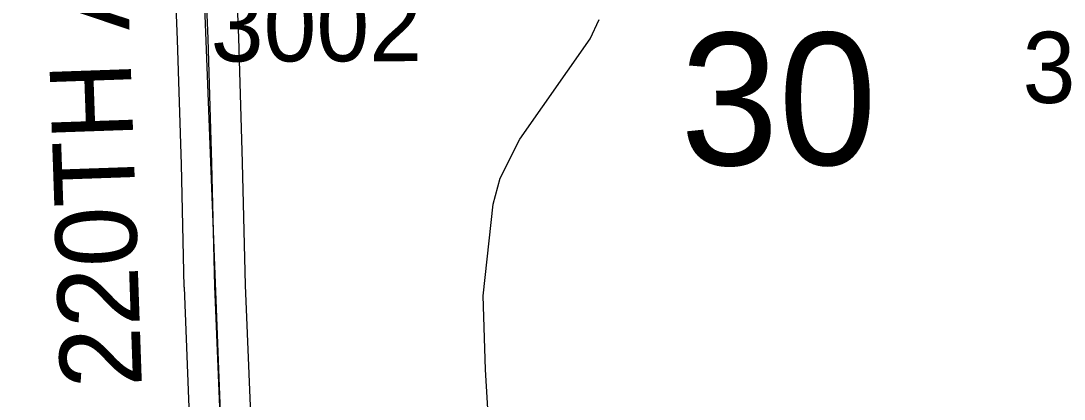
# Model space of a CAD drawing. Extents: x 128.7 to 185.5, y -21.4 to 12.6.
# Drawn here: x 145.758 to 146.785, y -0.12 to 0.252 of the extents above; entities that cross this region are included whole.
import ezdxf

# ---------------------------------------------------------------- set-up
doc = ezdxf.new("R2010")
doc.units = 0
for name, color, linetype in [('tdCoHydroRiver', 7, 'Continuous'), ('tdCoSecRdNmbr', 7, 'Continuous'), ('tdCoSecRdTxt', 7, 'Continuous'), ('tdCoSecRteBand', 7, 'Continuous'), ('tdCoSecRteCL', 7, 'Continuous'), ('tdCoSectLine', 7, 'Continuous'), ('tdCoSectNmbr', 7, 'Continuous'), ('tdCoSurfGravel', 7, 'Continuous'), ('tdCoTwpBndryShd', 7, 'Continuous')]:
    doc.layers.add(name, color=color, linetype=linetype)

msp = doc.modelspace()

# ---------------------------------------------------------------- linework, layer by layer
at = {"layer": 'tdCoHydroRiver'}
msp.add_lwpolyline([(146.2194, -0.1568), (146.2157, -0.0907), (146.2133, -0.0182), (146.223, 0.0721), (146.23, 0.0976), (146.2493, 0.1361), (146.3186, 0.2346), (146.3275, 0.2538)], dxfattribs=at)
at = {"layer": 'tdCoSecRteBand'}
for points in [[(145.7456, -0.323), (145.8648, -0.319), (145.9316, -0.3163), (145.9299, -0.2754), (145.9245, -0.1447), (145.9245, -0.1447), (145.9245, -0.1446), (145.9191, -0.0098), (145.919, -0.0095), (145.919, -0.0093), (145.9161, 0.1112), (145.9124, 0.2338), (145.907, 0.366), (145.9018, 0.4902), (145.8953, 0.626), (145.8953, 0.626), (145.8953, 0.626), (145.8953, 0.626), (145.8953, 0.6262), (145.7778, 0.6231), (145.7778, 0.6231), (145.7778, 0.6231), (145.6471, 0.6199)], [(145.9669, 0.3685), (145.9723, 0.2361), (145.9724, 0.2359), (145.9724, 0.2358), (145.9761, 0.1129), (145.9761, 0.1129), (145.9761, 0.1128), (145.979, -0.0076), (145.9844, -0.1422)]]:
    msp.add_lwpolyline(points, dxfattribs=at)
at = {"layer": 'tdCoSecRteCL'}
msp.add_lwpolyline([(145.9628, -0.3451), (145.9599, -0.2741), (145.9545, -0.1434), (145.949, -0.0085), (145.9461, 0.112), (145.9424, 0.2349), (145.9369, 0.3673), (145.9318, 0.4916), (145.9251, 0.6314), (145.9241, 0.6571)], dxfattribs=at)
at = {"layer": 'tdCoSectLine'}
msp.add_lwpolyline([(145.9237, 0.6571), (145.9624, -0.3451)], dxfattribs=at)
at = {"layer": 'tdCoSurfGravel'}
msp.add_lwpolyline([(145.9628, -0.3451), (145.9599, -0.2741), (145.9545, -0.1434), (145.949, -0.0085), (145.9461, 0.112), (145.9424, 0.2349), (145.9369, 0.3673), (145.9318, 0.4916), (145.9251, 0.6314), (145.9241, 0.6571), (145.9204, 0.7503), (145.9152, 0.9), (145.9098, 1.0311), (145.9046, 1.1586), (145.8985, 1.2896), (145.893, 1.423), (145.8896, 1.554), (145.8865, 1.6603)], dxfattribs=at)
at = {"layer": 'tdCoTwpBndryShd'}
msp.add_lwpolyline([(145.7753, 4.6779), (145.8126, 3.6695), (145.8481, 2.667), (145.8861, 1.6603), (145.9237, 0.6571), (145.9624, -0.3451), (146.001, -1.3445), (146.0324, -2.3549), (146.0614, -3.3563), (146.0903, -4.356), (146.1189, -5.3582), (146.1498, -6.358), (146.1796, -7.3579)], dxfattribs=at)

# ---------------------------------------------------------------- texts
at = {"layer": 'tdCoSecRdNmbr'}
for s, rotation, p in [('3002', 0.111, (145.945, 0.2123)), ('3010', 0.1116, (146.7444, 0.1715))]:
    msp.add_text(s, height=0.07, rotation=rotation, dxfattribs=at).set_placement(p)
at = {"layer": 'tdCoSecRdTxt'}
msp.add_text('220TH AVE', height=0.08, rotation=92, dxfattribs=at).set_placement((145.8773, -0.1073))
at = {"layer": 'tdCoSectNmbr'}
msp.add_text('30', height=0.13, rotation=0.1113, dxfattribs=at).set_placement((146.4075, 0.1103))

doc.saveas('drawing.dxf')
